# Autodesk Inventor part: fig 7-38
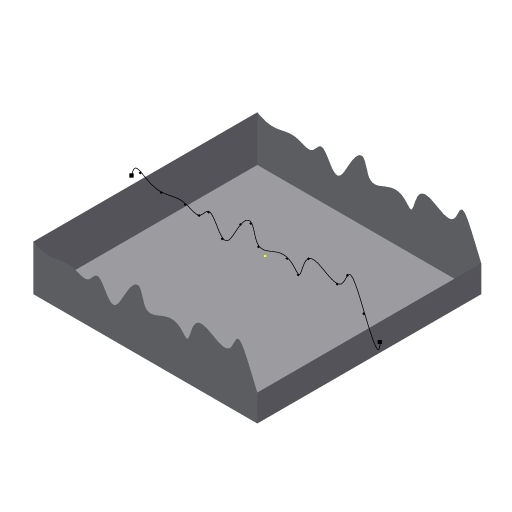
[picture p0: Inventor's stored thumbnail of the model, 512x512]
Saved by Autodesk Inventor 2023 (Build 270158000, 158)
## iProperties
Part Number: fig 7-38
Document SubType Name: Modeling
Created: 2002-12
Designer: deepak
Density: 1 g/cm^3
Material: Generic
Appearance: Default
Control State: 0
Master: False
Checked Out: False
Shininess: 64.0
Length Units: 11269
Angle Units: 11279
Time Units: 11290
Mass Units: 11283
Length Display Precision: 3
Angle Display Precision: 2
Compacted: True
Density: 0.0
Volumn: 0.0
Area: 0.0
PropertySet Name: Model Information
Author: cadcim
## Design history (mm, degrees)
sketch "Sketch1"
  geometry: L1 (-32.188, 30.089)-(27.812, 30.089); L2 (27.812, 30.089)-(27.812, -29.911); L3 (27.812, -29.911)-(-32.188, -29.911); L4 (-32.188, -29.911)-(-32.188, 30.089)
  constraints: 8 end point, 2 parallel, 1 horizontal, 1 perpendicular
  dimensions: "d0" = 60 distance of L1.start L1.end; "d1" = 60 distance of L3.end L1.start
extrude "Extrusion1" new body sketch "Sketch1" stored distance "d2" = 20; taper "d3" = 0 deg
sketch "Sketch2"
  geometry: 17 further points
  constraints: 17 other
extrude_surface "ExtrusionSrf1" sketch "Sketch2" dims "d4" = 70, "d5" = 0
split "Split1"
delete_face "Delete Face1"
node "Sketch5"
sketch "Sketch6"
  geometry: 1 further point
body "Srf1"
body "Srf2"
